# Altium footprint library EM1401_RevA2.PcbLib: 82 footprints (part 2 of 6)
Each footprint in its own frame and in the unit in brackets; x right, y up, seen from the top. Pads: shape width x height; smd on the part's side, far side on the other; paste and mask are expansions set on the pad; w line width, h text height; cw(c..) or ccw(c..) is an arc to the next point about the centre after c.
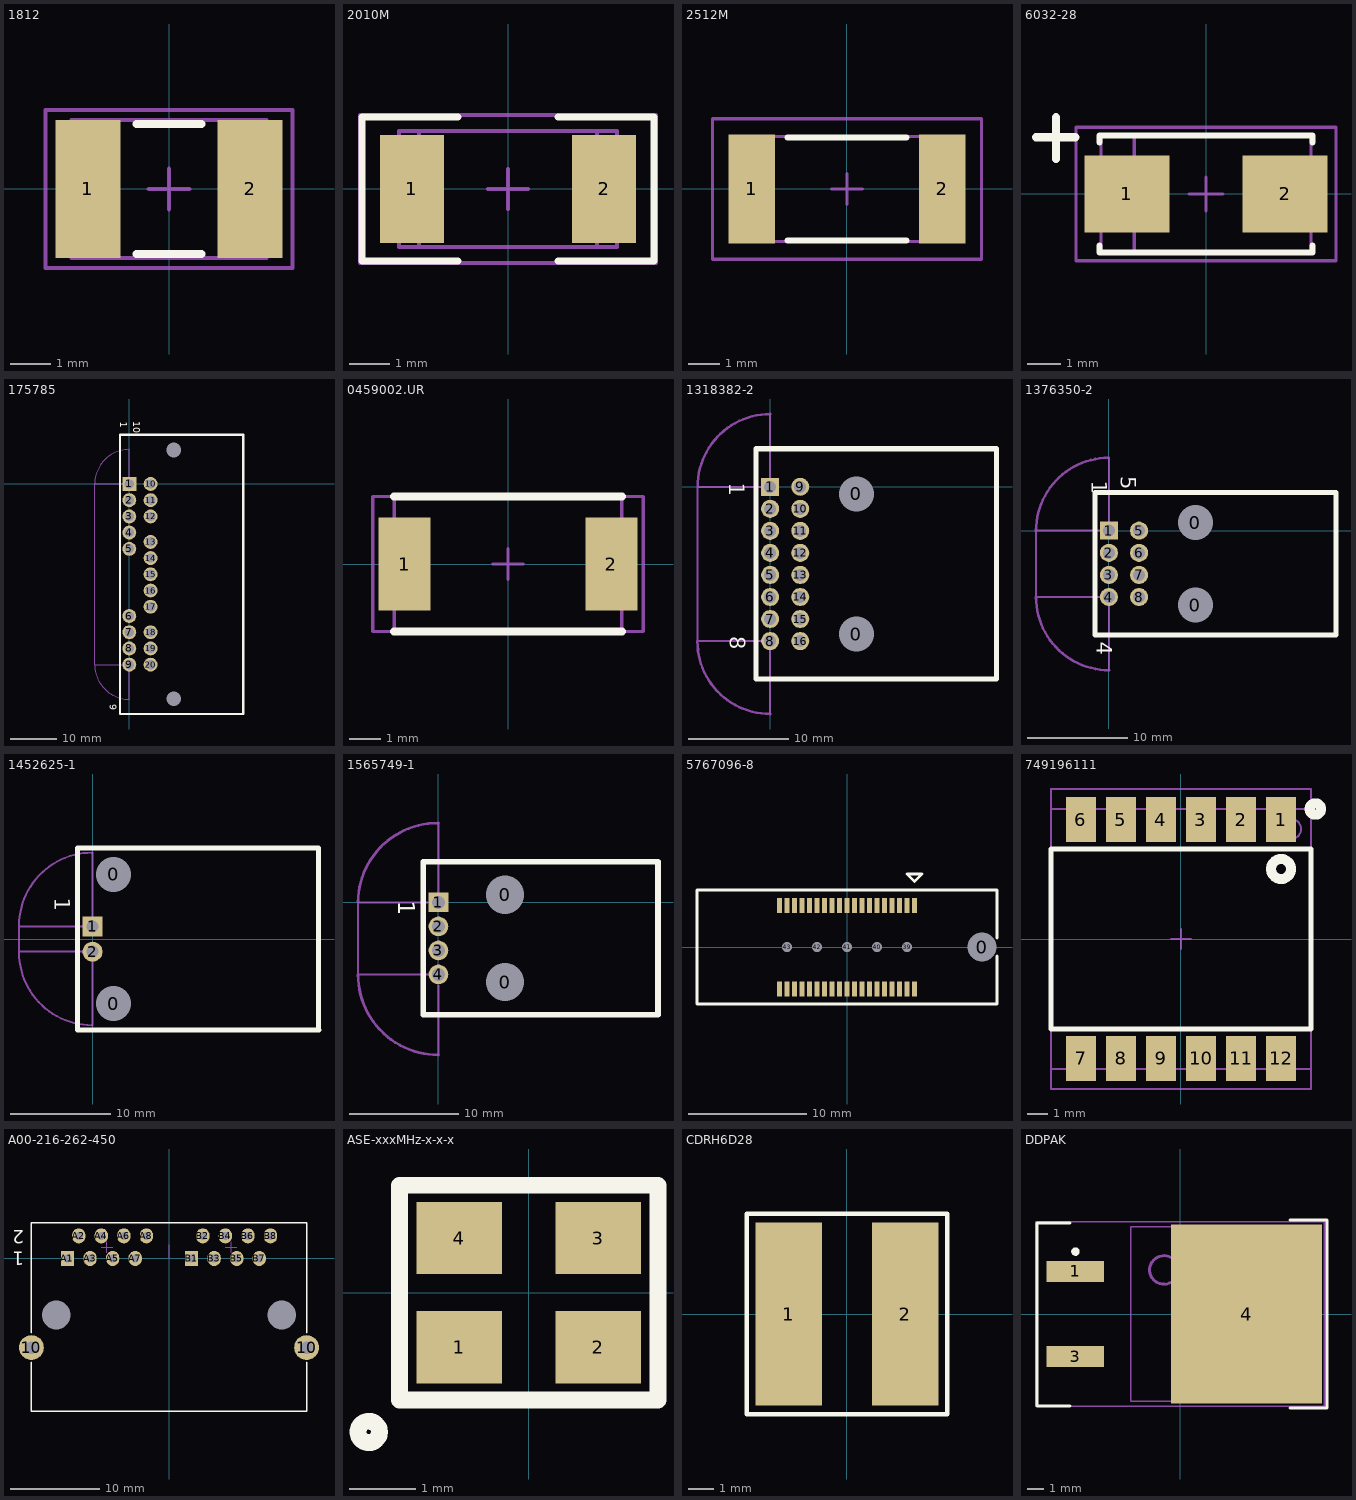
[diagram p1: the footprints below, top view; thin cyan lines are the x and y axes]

## 1812 [mm]
height 1.35
pads (2):
  rect 1.6x3.4 smd: 1(-2,0) 2(2,0)
Top Overlay:
  lines w0.2: -0.8,-1.6 0.8,-1.6 ; -0.8,1.6 0.8,1.6
Mechanical 5:
  text ".Designator" at -1.524,-0.508 h1.02
Mechanical 13:
  lines w0.1: -1.9,-1.7 -1.9,1.7 ; 1.9,-1.7 1.9,1.7 ; -2.4,-1.7 -2.4,1.7 2.4,1.7 2.4,-1.7 -2.4,-1.7
Mechanical 15:
  lines w0.1: -0.5,0 0.5,0 ; 0,-0.5 0,0.5 ; -3.05,-1.95 -3.05,1.95 3.05,1.95 3.05,-1.95 -3.05,-1.95
3D body: height 1.35, standoff 0, extent -2.399,-1.699 -1.901,1.699
3D body: height 1.35, standoff 0, extent -1.899,-1.699 1.899,1.699
3D body: height 1.35, standoff 0, extent 1.901,-1.699 2.399,1.699

## 2010M [mm]
height 0.71
pads (2):
  rect 1.6x2.7 smd: 1(-2.4,0) 2(2.4,0)
Top Overlay:
  lines w0.178: -1.25,-1.8 -3.65,-1.8 -3.65,1.8 -1.25,1.8 ; 1.25,-1.8 3.65,-1.8 3.65,1.8 1.25,1.8
Mechanical 5:
  text ".Designator" at -1.524,-0.508 h1.02
Mechanical 13:
  lines w0.1: -2.23,-1.45 -2.23,1.45 ; 2.23,-1.45 2.23,1.45 ; -2.73,-1.45 2.73,-1.45 2.73,1.45 -2.73,1.45 -2.73,-1.45
Mechanical 15:
  lines w0.1: -0.5,0 0.5,0 ; 0,-0.5 0,0.5 ; -3.7,-1.85 3.7,-1.85 3.7,1.85 -3.7,1.85 -3.7,-1.85
3D body: height 1.66, standoff 0, extent 2.231,-1.449 2.729,1.449
3D body: height 1.66, standoff 0, extent -2.229,-1.449 2.229,1.449
3D body: height 1.66, standoff 0, extent -2.729,-1.449 -2.231,1.449

## 2512M [mm] "Chip Resistor, Body 6.3x3.2mm, IPC Low Density"
height 0.71
pads (2):
  rect 1.5x3.5 smd: 1(-3.05,0) 2(3.05,0)
Top Overlay:
  lines w0.2: -1.9,-1.65 1.9,-1.65 ; -1.9,1.65 1.9,1.65
Mechanical 5:
  text ".Designator" at -1.524,-0.508 h1.02
Mechanical 13:
  lines w0.1: -2.463,-1.675 -2.463,1.675 ; 2.463,-1.675 2.463,1.675 ; -3.225,-1.675 3.225,-1.675 3.225,1.675 -3.225,1.675 -3.225,-1.675
Mechanical 15:
  lines w0.1: -0.5,0 0.5,0 ; 0,-0.5 0,0.5 ; -4.3,-2.25 4.3,-2.25 4.3,2.25 -4.3,2.25 -4.3,-2.25
3D body: height 0.71, standoff 0, extent 2.464,-1.674 3.224,1.674
3D body: height 0.71, standoff 0, extent -2.462,-1.674 2.462,1.674
3D body: height 0.71, standoff 0, extent -3.224,-1.674 -2.464,1.674

## 6032-28 [mm] "Medium Density IPC based on Vishay Sprague 293D datasheet."
height 2.8
pads (2):
  rect 2.55x2.3 smd: 1(-2.375,0) 2(2.375,0)
Top Overlay:
  lines w0.178: -3.2,-1.539 -3.2,-1.75 3.2,-1.75 3.2,-1.539 ; -3.2,1.539 -3.2,1.75 3.2,1.75 3.2,1.539
  lines w0.254: -5.1,1.7 -3.925,1.7 ; -4.5,1.05 -4.5,2.3
Mechanical 5:
  text ".Designator" at -1.524,-0.508 h1.02
Mechanical 13:
  lines w0.1: -2.15,-1.75 -2.15,1.75 ; -3.15,-1.75 3.15,-1.75 3.15,1.75 -3.15,1.75 -3.15,-1.75
Mechanical 15:
  lines w0.1: -0.5,0 0.5,0 ; 0,-0.5 0,0.5 ; -3.9,-2 3.9,-2 3.9,2 -3.9,2 -3.9,-2
3D body: height 2.8, standoff 2.8, extent -3.149,-1.749 -2.151,1.749
3D body: height 2.8, standoff 0, extent -3.15,-1.75 3.15,1.75

## 175785 [mm] ".070 SERIES MULTI-LOCK I/O CONN. 20Pos. PCB 90"
pads (22):
  round 1.524 hole 3.2 unplated: 0(9.6,-46.35) 0(9.6,7.35)
  rect 3x3 hole 2: 1(0,0)
  round 3 hole 2: 2(0,-3.5) 3(0,-7) 4(0,-10.5) 5(0,-14) 6(0,-28.5) 7(0,-32) 8(0,-35.5) 9(0,-39) 10(4.6,0) 11(4.6,-3.5) 12(4.6,-7) 13(4.6,-12.5) 14(4.6,-16) 15(4.6,-19.5) 16(4.6,-23) 17(4.6,-26.5) 18(4.6,-32) 19(4.6,-35.5) 20(4.6,-39)
Top Overlay:
  lines w0.508: -2,-49.65 -2,10.65 24.6,10.65 24.6,-49.65 -2,-49.65
  text "1" at -2.007,13.471 h1.52
  text "10" at 0.838,13.573 h1.52
  text "9" at -4.242,-47.514 h1.52
Mechanical 13:
  lines w0.2: -1.118,-38.989 -7.468,-38.989 -7.468,0 -1.118,0 ; 0,-46.482 0,-40.132 ; 0,1.118 0,7.468
  lines w0.254: -7.468,-38.989 ccw(c0.013,-39.002) 0,-46.482 ; -7.468,0 cw(c-0.013,-0.013) 0,7.442
3D body: height 15.93, standoff -3.9, extent -0.42,-49.65 24.5,10.65

## 0459002.UR [mil] "Series 459 Littlefuse SMT"
height 120
pads (2):
  rect 65x117 smd: 1(-130,0) 2(130,0)
Top Overlay:
  lines w10: -143,-85 143,-85 ; -143,85 143,85
Mechanical 13:
  lines w3.94: -143,-85 -143,85 143,85 143,-85 -143,-85
Mechanical 15:
  lines w3.94: -19.68,0 19.69,0 ; 0,-19.68 0,19.69 ; -170,-85 -170,85 170,85 170,-85 -170,-85
3D body: height 27.95, standoff 0, extent -143,-85 143,85

## 1318382-2 [mm] "Tyco 025 Series Multi-Lock Connector 16 position"
height 15.5
pads (18):
  round 3 hole 3.5 unplated: 0(8.6,-14.7) 0(8.6,-0.7)
  rect 1.8x1.8 hole 1.2: 1(0,0)
  round 1.8 hole 1.2: 2(0,-2.2) 3(0,-4.4) 4(0,-6.6) 5(0,-8.8) 6(0,-11) 7(0,-13.2) 8(0,-15.4) 9(3,0) 10(3,-2.2) 11(3,-4.4) 12(3,-6.6) 13(3,-8.8) 14(3,-11) 15(3,-13.2) 16(3,-15.4)
Top Overlay:
  lines w0.508: -1.4,-19.2 -1.4,3.8 22.6,3.8 22.6,-19.2 -1.4,-19.2
  text "1" at -4.077,0.414 h1.52
  text "8" at -4.026,-14.902 h1.52
Mechanical 13:
  lines w0.2: -0.914,-15.418 -7.264,-15.418 -7.264,0 -0.914,0 ; 0,-22.682 0,-16.332 ; 0,0.914 0,7.264
  lines w0.254: -7.264,-15.418 ccw(c0,-15.418) 0,-22.682 ; -7.239,0 cw(c0.013,0.013) 0,7.264
3D body: height 15.6, standoff -3.9, extent -0.3,-19.3 24.17,3.7

## 1376350-2 [mm] "Tyco 025 Series Multi-Lock Connector 8 position"
height 15.5
pads (10):
  round 3 hole 3.5 unplated: 0(8.6,-7.4) 0(8.6,0.8)
  rect 1.8x1.8 hole 1.2: 1(0,0)
  round 1.8 hole 1.2: 2(0,-2.2) 3(0,-4.4) 4(0,-6.6) 5(3,0) 6(3,-2.2) 7(3,-4.4) 8(3,-6.6)
Top Overlay:
  lines w0.508: -1.4,-10.4 -1.4,3.8 22.6,3.8 22.6,-10.4 -1.4,-10.4
  text "1" at -1.727,4.992 h1.52
  text "5" at 1.169,5.424 h1.52
  text "4" at -1.219,-11.061 h1.52
Mechanical 13:
  lines w0.2: -0.94,-6.604 -7.264,-6.604 -7.264,0 -0.914,0 ; 0,-13.894 0,-7.544 ; 0,0.914 0,7.264
  lines w0.254: -7.264,-6.604 ccw(c0.025,-6.604) 0.025,-13.894 ; -7.264,0 cw(c0,0) 0,7.264
3D body: height 15.6, standoff -3.9, extent -0.3,-10.4 24.17,3.8

## 1452625-1 [mm] "Tyco Automotive, Unsealed PCB Horizontal HDR, 2x1"
height 11.3
pads (4):
  round 3 hole 3.5 unplated: 0(2.1,-6.47) 0(2.1,6.47)
  rect 2x2 hole 1.2: 1(0,1.27)
  round 2 hole 1.2: 2(0,-1.27)
Top Overlay:
  lines w0.508: 22.57,9.098 -1.5,9.098 -1.5,-9.098 22.67,-9.098 ; 22.62,-9.098 22.62,9.098
  text "1" at -3.77,4.13 h1.52
Mechanical 13:
  lines w0.2: -7.366,-1.27 -1.016,-1.27 0,-2.286 0,-8.661 ; -7.366,1.27 -1.016,1.27 0,2.286 0,8.636 ; -0.051,-8.636 cw(c-0.051,-1.321) -7.366,-1.321 -7.366,1.321 cw(c-0.04,1.321) -0.04,8.647 ; -0.051,-8.573 0,-8.573 ; -0.04,8.573 0,8.573
3D body: height 11.2, standoff -3.65, extent -0.53,-9.098 22.62,9.098

## 1565749-1 [mm] "Tyco 025 Series Multi-Lock Connector 4 position"
height 12.5
pads (6):
  round 3 hole 3.5 unplated: 0(6.1,-7.3) 0(6.1,0.7)
  rect 1.8x1.8 hole 1.2: 1(0,0)
  round 1.8 hole 1.2: 2(0,-2.2) 3(0,-4.4) 4(0,-6.6)
Top Overlay:
  lines w0.508: -1.4,-10.3 -1.4,3.7 20.1,3.7 20.1,-10.3 -1.4,-10.3
  text "1" at -3.668,0.139 h1.52
Mechanical 13:
  lines w0.2: -7.366,0 -1.016,0 ; -7.366,0.025 -7.366,-6.604 -1.016,-6.604 ; 0,-13.97 0,-7.62 ; 0,0.914 0,7.264
  lines w0.254: -7.366,-6.604 ccw(c0,-6.604) 0,-13.97 ; -7.366,0.025 cw(c-0.064,-0.038) 0,7.264
3D body: height 12.58, standoff -3.92, extent -0.35,-10.3 21.94,3.7

## 5767096-8 [mil] "Mictor connector 38 pos receptacle"
pads (44):
  round 94 hole 96: 0(450,0)
  rect 17x50 smd: 1(225,139) 2(225,-139) 3(200,139) 4(200,-139) 5(175,139) 6(175,-139) 7(150,139) 8(150,-139) 9(125,139) 10(125,-139) 11(100,139) 12(100,-139) 13(75,139) 14(75,-139) 15(50,139) 16(50,-139) 17(25,139) 18(25,-139) 19(0,139) 20(0,-139) 21(-25,139) 22(-25,-139) 23(-50,139) 24(-50,-139) 25(-75,139) 26(-75,-139) 27(-100,139) 28(-100,-139) 29(-125,139) 30(-125,-139) 31(-150,139) 32(-150,-139) 33(-175,139) 34(-175,-139) 35(-200,139) 36(-200,-139) 37(-225,139) 38(-225,-139)
  round 32 hole 34: 39(200,0) 40(100,0) 41(0,0) 42(-100,0) 43(-200,0)
Top Overlay:
  lines w10: 500,-30 500,-190 -500,-190 -500,190 0,190 500,190 500,30 ; 200,244 250,244 225,219 200,244
3D body: height 240, standoff -51, extent -500,-172 500,171

## 749196111 [mm] "flyback transformer"
height 6.2
pads (12):
  rect 1.5x2.25 smd: 1(5,5.975) 2(3,5.975) 3(1,5.975) 4(-1,5.975) 5(-3,5.975) 6(-5,5.975) 7(-5,-5.975) 8(-3,-5.975) 9(-1,-5.975) 10(1,-5.975) 11(3,-5.975) 12(5,-5.975)
Top Overlay:
  circle w0.5: c6.715,6.5 r0.285
  circle w0.5: c5,3.5 r0.5
  lines w0.254: -6.5,-4.5 6.5,-4.5 6.5,4.5 -6.5,4.5 -6.5,-4.5
Mechanical 5:
  text ".designator" at -4.5,-2 h1.02
Mechanical 13:
  circle w0.1: c5.5,5.5 r0.5
  lines w0.1: -6.5,-6.5 6.5,-6.5 6.5,6.5 -6.5,6.5 -6.5,-6.5
Mechanical 15:
  lines w0.1: -0.5,0 0.5,0 ; 0,-0.5 0,0.5 ; -6.5,-7.5 6.5,-7.5 6.5,7.5 -6.5,7.5 -6.5,-7.5
3D body: height 11.43, standoff 0.25, extent -6.5,-6.5 6.5,6.5

## A00-216-262-450 [mm] "CONN RJ45 MODJACK 1X2 R/A SHIELD"
height 13.792
pads (20):
  round 0 hole 3.251 unplated: 0(-12.7,-6.35) 0(12.7,-6.35)
  round 2.794 hole 1.397: 10(-15.494,-10.033) 10(15.494,-10.033)
  rect 1.5x1.7 hole 0.9: A1(-11.43,0) B1(2.54,0)
  oval 1.5x1.7 hole 0.9: A2(-10.16,2.54) A3(-8.89,0) A4(-7.62,2.54) A5(-6.35,0) A6(-5.08,2.54) A7(-3.81,0) A8(-2.54,2.54) B2(3.81,2.54) B3(5.08,0) B4(6.35,2.54) B5(7.62,0) B6(8.89,2.54) B7(10.16,0) B8(11.43,2.54)
Top Overlay:
  lines w0.178: -15.494,-11.684 -15.494,-17.221 15.494,-17.221 15.494,-11.684 ; -15.494,-8.382 -15.494,4.039 15.494,4.039 15.494,-8.382
  text "2" at -16.285,3.19 h1.52
  text "1" at -16.31,0.73 h1.52
Mechanical 5:
  text ".designator" at -5.436,-6.274 h1.02
Mechanical 15:
  lines w0.127: -7.62,1.27 -6.985,1.27 ; -6.985,0.635 -6.985,1.27 ; -6.985,1.905 -6.985,1.27 ; -6.35,1.27 -6.985,1.27 ; 0,0 0,1.549 ; 6.35,1.27 6.985,1.27 ; 6.985,0.635 6.985,1.27 ; 6.985,1.905 6.985,1.27 ; 7.62,1.27 6.985,1.27
3D body: height 1.81, standoff -15.49, extent -15.494,-17.221 15.626,4.049

## ASE-xxxMHz-x-x-x [mil] "ASE 3.3Vdc CMOS SMD crystal oscillator"
pads (4):
  rect 51x43 smd: 1(-41.5,-32.5) 2(41.5,-32.5) 3(41.5,32.5) 4(-41.5,32.5)
Top Overlay:
  circle w10: c-95.4,-83 r6.4
  lines w10: -77,-64 77,-64 77,64 -77,64 -77,-64
Mechanical 5:
  text ".Designator" at -60,-20 h40

## CDRH6D28 [mm] "Sumida reommended land pattern"
height 3
pads (2):
  rect 2.65x7.3 smd: 1(-2.325,0) 2(2.325,0)
Top Overlay:
  lines w0.178: -4,-4 0,-4 4,-4 4,0 4,4 0,4 -4,4 -4,0 -4,-4
Mechanical 5:
  text ".Designator" at -1.524,-0.508 h1.02
3D body: height 3, standoff 0, extent -3.5,-3.5 3.5,3.5

## DDPAK [mil] "D2-PAK, 3-Pads, Body 9.7x10.4mm (max), IPC Medium Density, using Vishay Silionix recommended pad sizes"
height 190
pads (3):
  rect 135x49.49 smd: 1(-246.06,100) 3(-246.06,-100)
  rect 355x420 smd: 4(155.51,0)
Top Overlay:
  circle w9.84: c-246.06,146.4 r4.92
  lines w7: -258.39,-216.1 -336.8,-216.1 -336.8,214.12 -258.39,214.12 ; 258.09,-220.47 344,-220.47 344,220.47 258.09,220.47
Mechanical 5:
  text ".Designator" at -60,-20 h40
Mechanical 13:
  circle w7: c-38.39,103.35 r33.52
  lines w3.94: -116.14,-204.72 -116.14,204.72 263.78,204.72 263.78,-204.72 -116.14,-204.72
Mechanical 15:
  lines w3.94: -19.69,0 19.68,0 ; 0,-19.68 0,19.68 ; -338.58,-216.54 -338.58,216.54 338.58,216.54 338.58,-216.54 -338.58,-216.54
3D body: height 190, standoff 10, extent -116.14,-204.72 263.78,204.72
3D body: height 190.01, standoff 190, extent -72.18,69.56 -4.59,137.14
